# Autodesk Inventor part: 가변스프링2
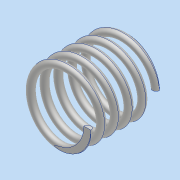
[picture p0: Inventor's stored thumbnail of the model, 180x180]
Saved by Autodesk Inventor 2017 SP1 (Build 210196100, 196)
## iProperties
Part Number: 가변스프링2
Material: 알루미늄 6061
Document SubType Name: Modeling
Designer: MRC
Density: 2.7 g/cm^3
Appearance: 알루미늄 - 평지
Mass: 2.34993 g
Surface Area: 17.6923 cm^2
Volume: 0.870346 cm^3
Author: MRC
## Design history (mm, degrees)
sketch "스케치1"
  geometry: L1 (0, 0)-(0, 19.5); L2 (0, 19.5)-(9, 19.5); L3 (0, 0)-(9, 0); C1 r 1 at (9, 0)
  constraints: 6 end point, 1 centre point, 1 coincident, 1 horizontal, 1 perpendicular, 1 vertical
  dimensions: "d0" = 19.5 distance of L1.start L1.end (derived); "d1" = 9 distance of L1.end L2.end; "d2" = 9 distance of L1.start L3.end; "d3" = 2 diameter of C1
feature "코일1" pitch "d4" = 10; turns "d6" = 5; dims "d5" = 19.5 (= d0), "d7" = 0, angle "d8" = 90 deg, angle "d9" = 90 deg, "d10" = 0, "d11" = 0
sketch "스케치2"
  geometry: L1 (19.5, 15)-(0, 15); L2 (0, 15)-(0, -15); L3 (0, -15)-(19.5, -15); L4 (19.5, -15)-(19.5, 15); 2 further points
  constraints: 8 end point, 2 midpoint, 2 parallel, 1 coincident, 1 horizontal, 1 perpendicular
  dimensions: "d12" = 30 distance of L3.end L1.start; "d13" = 19.5 distance of L1.start L1.end (= d0)
extrude "돌출2" sketch "스케치2" stored distance "d16" = 0; taper "d17" = 0 deg
node "솔리드1"
